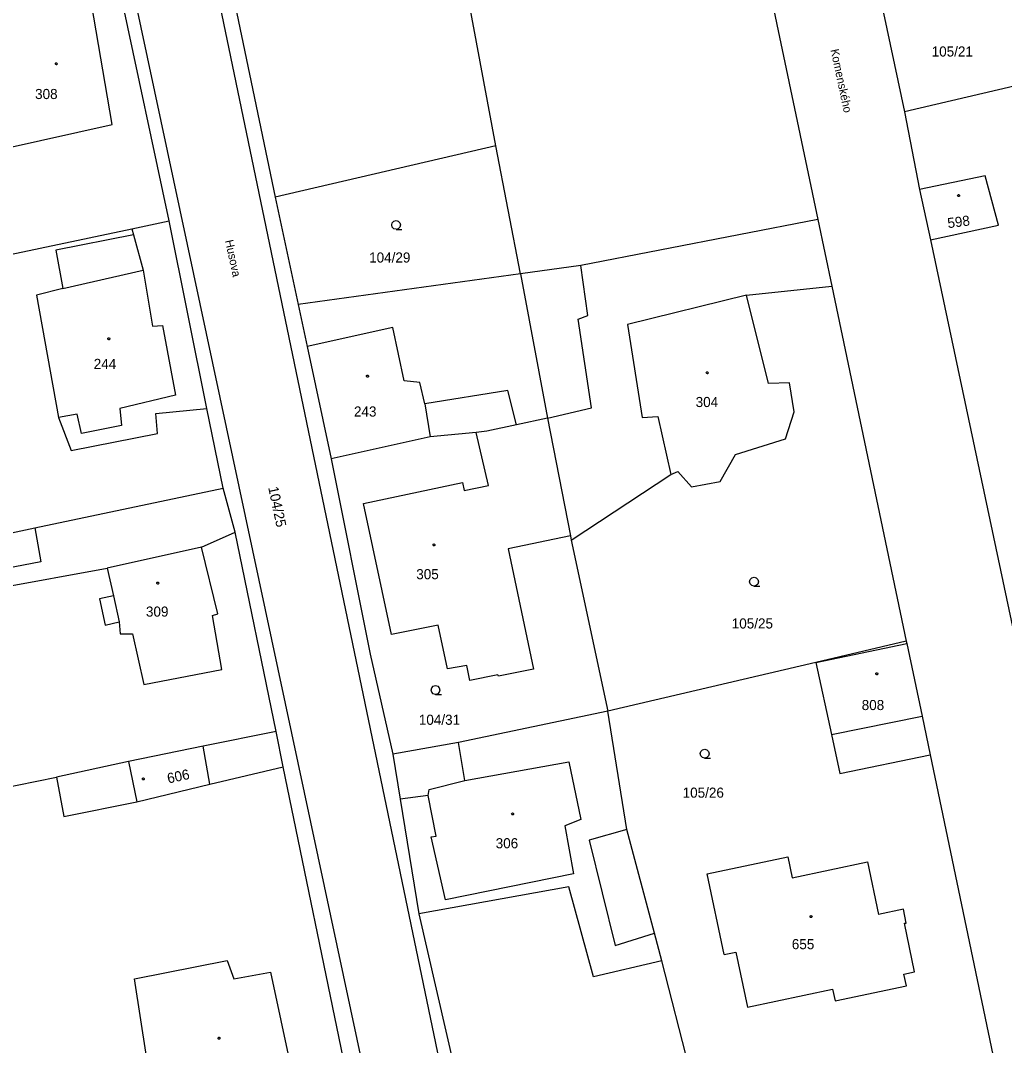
# Model space of a CAD drawing. Extents: x -757994 to -755874, y -1047691 to -1046119.
# Drawn here: x -756719.4 to -756636.5, y -1047241.1 to -1047154.8 of the extents above; entities that cross this region are included whole.
import ezdxf

# ---------------------------------------------------------------- set-up
doc = ezdxf.new("R2010")
doc.units = 0
doc.layers.add('katastrální mapa', color=7, linetype='Continuous')

msp = doc.modelspace()

# ---------------------------------------------------------------- linework, layer by layer
at = {"layer": 'katastrální mapa'}
for p, q in [((-756664.1, -1047115.15), (-756652.26, -1047171.56)), ((-756680.25, -1047261.01), (-756708.55, -1047124.95)), ((-756715.54, -1047126.13), (-756686.13, -1047263.87)), ((-756679.39, -1047165.36), (-756684.75, -1047136.4)), ((-756704.43, -1047138.76), (-756697.98, -1047169.68)), ((-756647.93, -1047148.48), (-756644.94, -1047162.5)), ((-756706.92, -1047171.68), (-756710.99, -1047152.52)), ((-756711.7, -1047163.55), (-756713.46, -1047153.37)), ((-756635.71, -1047160.32), (-756644.94, -1047162.5)), ((-756644.94, -1047162.5), (-756643.68, -1047169.02)), ((-756720.64, -1047165.55), (-756711.7, -1047163.55)), ((-756679.39, -1047165.36), (-756697.98, -1047169.68)), ((-756677.3, -1047176.13), (-756679.39, -1047165.36)), ((-756638.16, -1047167.89), (-756643.68, -1047169.02)), ((-756637.03, -1047172.04), (-756638.16, -1047167.89)), ((-756697.98, -1047169.68), (-756696.03, -1047178.72)), ((-756643.68, -1047169.02), (-756642.75, -1047173.28)), ((-756710.05, -1047172.34), (-756706.92, -1047171.68)), ((-756703.73, -1047187.47), (-756706.92, -1047171.68)), ((-756652.26, -1047171.56), (-756672.23, -1047175.43)), ((-756652.26, -1047171.56), (-756651.08, -1047177.17)), ((-756642.75, -1047173.28), (-756637.03, -1047172.04)), ((-756732.68, -1047177.09), (-756710.05, -1047172.34)), ((-756709.91, -1047172.84), (-756716.47, -1047174.14)), ((-756710.05, -1047172.34), (-756709.91, -1047172.84)), ((-756709.91, -1047172.84), (-756709.11, -1047175.82)), ((-756642.75, -1047173.28), (-756629.71, -1047234.91)), ((-756716.47, -1047174.14), (-756715.88, -1047177.36)), ((-756672.23, -1047175.43), (-756677.3, -1047176.13)), ((-756671.63, -1047179.65), (-756672.23, -1047175.43)), ((-756715.88, -1047177.36), (-756709.11, -1047175.82)), ((-756709.11, -1047175.82), (-756708.32, -1047180.53)), ((-756677.3, -1047176.13), (-756696.03, -1047178.72)), ((-756677.3, -1047176.13), (-756675.03, -1047188.29)), ((-756715.88, -1047177.36), (-756718.1, -1047177.93)), ((-756658.25, -1047177.94), (-756651.08, -1047177.17)), ((-756651.08, -1047177.17), (-756644.8, -1047207.08)), ((-756718.1, -1047177.93), (-756716.22, -1047188.23)), ((-756658.25, -1047177.94), (-756668.29, -1047180.39)), ((-756656.41, -1047185.36), (-756658.25, -1047177.94)), ((-756696.03, -1047178.72), (-756695.27, -1047182.26)), ((-756672.44, -1047179.95), (-756671.63, -1047179.65)), ((-756671.32, -1047187.43), (-756672.44, -1047179.95)), ((-756708.32, -1047180.53), (-756707.48, -1047180.47)), ((-756707.48, -1047180.47), (-756706.36, -1047186.34)), ((-756688.07, -1047180.64), (-756695.27, -1047182.26)), ((-756687.11, -1047185.15), (-756688.07, -1047180.64)), ((-756668.29, -1047180.39), (-756667.06, -1047188.23)), ((-756695.27, -1047182.26), (-756693.27, -1047191.71)), ((-756685.79, -1047185.27), (-756687.11, -1047185.15)), ((-756685.36, -1047187.08), (-756685.79, -1047185.27)), ((-756678.37, -1047185.95), (-756685.36, -1047187.08)), ((-756677.65, -1047188.85), (-756678.37, -1047185.95)), ((-756654.65, -1047185.32), (-756656.41, -1047185.36)), ((-756654.24, -1047187.74), (-756654.65, -1047185.32)), ((-756706.36, -1047186.34), (-756711.07, -1047187.46)), ((-756711.07, -1047187.46), (-756710.91, -1047188.9)), ((-756708.04, -1047187.9), (-756703.73, -1047187.47)), ((-756702.37, -1047194.18), (-756703.73, -1047187.47)), ((-756685.36, -1047187.08), (-756684.91, -1047189.85)), ((-756675.03, -1047188.29), (-756671.32, -1047187.43)), ((-756654.98, -1047190.04), (-756654.24, -1047187.74)), ((-756714.65, -1047187.96), (-756716.22, -1047188.23)), ((-756716.22, -1047188.23), (-756715.17, -1047191.02)), ((-756714.29, -1047189.57), (-756714.65, -1047187.96)), ((-756707.89, -1047189.58), (-756708.04, -1047187.9)), ((-756675.03, -1047188.29), (-756677.65, -1047188.85)), ((-756675.03, -1047188.29), (-756673.1, -1047198.2)), ((-756667.06, -1047188.23), (-756665.74, -1047188.14)), ((-756665.74, -1047188.14), (-756664.63, -1047193.02)), ((-756715.17, -1047191.02), (-756707.89, -1047189.58)), ((-756710.91, -1047188.9), (-756714.29, -1047189.57)), ((-756681.03, -1047189.48), (-756684.91, -1047189.85)), ((-756680.14, -1047189.39), (-756681.03, -1047189.48)), ((-756680, -1047193.95), (-756681.03, -1047189.48)), ((-756677.65, -1047188.85), (-756680.14, -1047189.39)), ((-756684.91, -1047189.85), (-756693.27, -1047191.71)), ((-756659.18, -1047191.36), (-756654.98, -1047190.04)), ((-756693.27, -1047191.71), (-756689.98, -1047208.15)), ((-756660.48, -1047193.61), (-756659.18, -1047191.36)), ((-756673.03, -1047198.55), (-756664.63, -1047193.02)), ((-756664.63, -1047193.02), (-756664.06, -1047192.79)), ((-756664.06, -1047192.79), (-756662.9, -1047194.06)), ((-756690.52, -1047195.47), (-756682.18, -1047193.71)), ((-756682.18, -1047193.71), (-756682.04, -1047194.38)), ((-756662.9, -1047194.06), (-756660.48, -1047193.61)), ((-756718.23, -1047197.51), (-756702.37, -1047194.18)), ((-756701.35, -1047197.89), (-756702.37, -1047194.18)), ((-756682.04, -1047194.38), (-756680, -1047193.95)), ((-756688.17, -1047206.5), (-756690.52, -1047195.47)), ((-756724.76, -1047198.92), (-756718.23, -1047197.51)), ((-756718.23, -1047197.51), (-756717.71, -1047200.39)), ((-756704.19, -1047199.16), (-756701.35, -1047197.89)), ((-756697.89, -1047214.67), (-756701.35, -1047197.89)), ((-756673.1, -1047198.2), (-756678.34, -1047199.29)), ((-756673.1, -1047198.2), (-756673.03, -1047198.55)), ((-756673.03, -1047198.55), (-756669.94, -1047212.95)), ((-756704.19, -1047199.16), (-756712.12, -1047200.91)), ((-756702.82, -1047204.76), (-756704.19, -1047199.16)), ((-756678.34, -1047199.29), (-756676.21, -1047209.42)), ((-756717.71, -1047200.39), (-756724.35, -1047201.65)), ((-756732.5, -1047204.62), (-756712.12, -1047200.91)), ((-756712.12, -1047200.91), (-756711.6, -1047203.25)), ((-756711.6, -1047203.25), (-756712.77, -1047203.51)), ((-756711.6, -1047203.25), (-756711.12, -1047205.45)), ((-756712.77, -1047203.51), (-756712.29, -1047205.71)), ((-756703.26, -1047204.91), (-756702.82, -1047204.76)), ((-756702.47, -1047209.46), (-756703.26, -1047204.91)), ((-756712.29, -1047205.71), (-756711.12, -1047205.45)), ((-756711.12, -1047205.45), (-756711.03, -1047206.46)), ((-756684.25, -1047205.72), (-756688.17, -1047206.5)), ((-756683.45, -1047209.4), (-756684.25, -1047205.72)), ((-756711.03, -1047206.46), (-756709.99, -1047206.45)), ((-756709.99, -1047206.45), (-756709.03, -1047210.72)), ((-756644.8, -1047207.08), (-756652.41, -1047208.86)), ((-756652.41, -1047208.86), (-756644.76, -1047207.26)), ((-756644.8, -1047207.08), (-756644.76, -1047207.26)), ((-756644.76, -1047207.26), (-756643.47, -1047213.38)), ((-756689.98, -1047208.15), (-756688.05, -1047216.58)), ((-756681.83, -1047209.12), (-756683.45, -1047209.4)), ((-756681.56, -1047210.39), (-756681.83, -1047209.12)), ((-756676.21, -1047209.42), (-756679.17, -1047210.02)), ((-756652.41, -1047208.86), (-756669.94, -1047212.95)), ((-756652.41, -1047208.86), (-756651.1, -1047214.94)), ((-756709.03, -1047210.72), (-756702.47, -1047209.46)), ((-756679.21, -1047209.89), (-756681.56, -1047210.39)), ((-756679.17, -1047210.02), (-756679.21, -1047209.89)), ((-756669.94, -1047212.95), (-756682.54, -1047215.61)), ((-756668.33, -1047222.93), (-756669.94, -1047212.95)), ((-756651.1, -1047214.94), (-756643.47, -1047213.38)), ((-756643.47, -1047213.38), (-756642.79, -1047216.64)), ((-756697.89, -1047214.67), (-756704.05, -1047215.9)), ((-756697.29, -1047217.65), (-756697.89, -1047214.67)), ((-756651.1, -1047214.94), (-756650.39, -1047218.22)), ((-756704.05, -1047215.9), (-756710.33, -1047217.21)), ((-756703.49, -1047219.12), (-756704.05, -1047215.9)), ((-756682.54, -1047215.61), (-756688.05, -1047216.58)), ((-756681.99, -1047218.79), (-756682.54, -1047215.61)), ((-756688.05, -1047216.58), (-756687.44, -1047220.36)), ((-756650.39, -1047218.22), (-756642.79, -1047216.64)), ((-756642.79, -1047216.64), (-756637.5, -1047241.9)), ((-756710.33, -1047217.21), (-756716.41, -1047218.52)), ((-756710.33, -1047217.21), (-756709.62, -1047220.59)), ((-756703.49, -1047219.12), (-756697.29, -1047217.65)), ((-756687.61, -1047264.59), (-756697.29, -1047217.65)), ((-756681.99, -1047218.79), (-756673.22, -1047217.23)), ((-756673.22, -1047217.23), (-756672.23, -1047222.1)), ((-756729.73, -1047221.2), (-756716.41, -1047218.52)), ((-756716.41, -1047218.52), (-756715.78, -1047221.82)), ((-756685.01, -1047219.55), (-756681.99, -1047218.79)), ((-756709.62, -1047220.59), (-756703.49, -1047219.12)), ((-756685.07, -1047220.06), (-756685.01, -1047219.55)), ((-756715.78, -1047221.82), (-756709.62, -1047220.59)), ((-756685.07, -1047220.06), (-756687.44, -1047220.36)), ((-756687.44, -1047220.36), (-756685.88, -1047230.02)), ((-756684.4, -1047223.49), (-756685.07, -1047220.06)), ((-756672.23, -1047222.1), (-756673.57, -1047222.62)), ((-756673.57, -1047222.62), (-756672.84, -1047226.65)), ((-756668.33, -1047222.93), (-756671.52, -1047223.84)), ((-756666.01, -1047231.67), (-756668.33, -1047222.93)), ((-756684.84, -1047223.55), (-756684.4, -1047223.49)), ((-756683.63, -1047228.86), (-756684.84, -1047223.55)), ((-756671.52, -1047223.84), (-756669.32, -1047232.7)), ((-756661.57, -1047226.66), (-756654.77, -1047225.24)), ((-756654.77, -1047225.24), (-756654.4, -1047227)), ((-756654.4, -1047227), (-756648.07, -1047225.66)), ((-756648.07, -1047225.66), (-756647.15, -1047230.09)), ((-756672.84, -1047226.65), (-756683.63, -1047228.86)), ((-756660.15, -1047233.46), (-756661.57, -1047226.66)), ((-756673.23, -1047227.76), (-756685.88, -1047230.02)), ((-756671.15, -1047235.33), (-756673.23, -1047227.76)), ((-756685.88, -1047230.02), (-756679.1, -1047259.48)), ((-756645.04, -1047229.65), (-756647.15, -1047230.09)), ((-756644.8, -1047230.83), (-756645.04, -1047229.65)), ((-756644.1, -1047234.92), (-756644.96, -1047230.83)), ((-756644.96, -1047230.83), (-756644.8, -1047230.83)), ((-756669.32, -1047232.7), (-756666.01, -1047231.67)), ((-756665.39, -1047234), (-756666.01, -1047231.67)), ((-756660.15, -1047233.46), (-756659.16, -1047233.25)), ((-756659.16, -1047233.25), (-756658.19, -1047237.88)), ((-756709.83, -1047235.51), (-756702.02, -1047233.96)), ((-756702.02, -1047233.96), (-756701.46, -1047235.5)), ((-756665.39, -1047234), (-756671.15, -1047235.33)), ((-756660.84, -1047251.74), (-756665.39, -1047234)), ((-756701.46, -1047235.5), (-756698.36, -1047234.94)), ((-756698.36, -1047234.94), (-756695.91, -1047246.38)), ((-756644.99, -1047235.11), (-756644.1, -1047234.92)), ((-756644.78, -1047236.09), (-756644.99, -1047235.11)), ((-756708.81, -1047242.06), (-756709.83, -1047235.51)), ((-756650.79, -1047237.35), (-756644.78, -1047236.09)), ((-756658.19, -1047237.88), (-756651, -1047236.37)), ((-756651, -1047236.37), (-756650.79, -1047237.35))]:
    msp.add_line(p, q, dxfattribs=at)
for points in [[(-756716.41, -1047158.355), (-756716.36, -1047158.365), (-756716.335, -1047158.41), (-756716.325, -1047158.44), (-756716.335, -1047158.485), (-756716.375, -1047158.52), (-756716.41, -1047158.525), (-756716.455, -1047158.51), (-756716.485, -1047158.48), (-756716.495, -1047158.44), (-756716.485, -1047158.395), (-756716.445, -1047158.36)], [(-756640.39, -1047169.455), (-756640.34, -1047169.465), (-756640.315, -1047169.51), (-756640.305, -1047169.54), (-756640.315, -1047169.585), (-756640.355, -1047169.62), (-756640.39, -1047169.625), (-756640.435, -1047169.61), (-756640.465, -1047169.58), (-756640.475, -1047169.54), (-756640.465, -1047169.495), (-756640.425, -1047169.46)], [(-756711.99, -1047181.515), (-756711.94, -1047181.525), (-756711.915, -1047181.57), (-756711.905, -1047181.6), (-756711.915, -1047181.645), (-756711.955, -1047181.68), (-756711.99, -1047181.685), (-756712.035, -1047181.67), (-756712.065, -1047181.64), (-756712.075, -1047181.6), (-756712.065, -1047181.555), (-756712.025, -1047181.52)], [(-756661.56, -1047184.375), (-756661.51, -1047184.385), (-756661.485, -1047184.43), (-756661.475, -1047184.46), (-756661.485, -1047184.505), (-756661.525, -1047184.54), (-756661.56, -1047184.545), (-756661.605, -1047184.53), (-756661.635, -1047184.5), (-756661.645, -1047184.46), (-756661.635, -1047184.415), (-756661.595, -1047184.38)], [(-756690.2, -1047184.665), (-756690.15, -1047184.675), (-756690.125, -1047184.72), (-756690.115, -1047184.75), (-756690.125, -1047184.795), (-756690.165, -1047184.83), (-756690.2, -1047184.835), (-756690.245, -1047184.82), (-756690.275, -1047184.79), (-756690.285, -1047184.75), (-756690.275, -1047184.705), (-756690.235, -1047184.67)], [(-756684.6, -1047198.875), (-756684.55, -1047198.885), (-756684.525, -1047198.93), (-756684.515, -1047198.96), (-756684.525, -1047199.005), (-756684.565, -1047199.04), (-756684.6, -1047199.045), (-756684.645, -1047199.03), (-756684.675, -1047199), (-756684.685, -1047198.96), (-756684.675, -1047198.915), (-756684.635, -1047198.88)], [(-756707.87, -1047202.095), (-756707.82, -1047202.105), (-756707.795, -1047202.15), (-756707.785, -1047202.18), (-756707.795, -1047202.225), (-756707.835, -1047202.26), (-756707.87, -1047202.265), (-756707.915, -1047202.25), (-756707.945, -1047202.22), (-756707.955, -1047202.18), (-756707.945, -1047202.135), (-756707.905, -1047202.1)], [(-756647.28, -1047209.725), (-756647.23, -1047209.735), (-756647.205, -1047209.78), (-756647.195, -1047209.81), (-756647.205, -1047209.855), (-756647.245, -1047209.89), (-756647.28, -1047209.895), (-756647.325, -1047209.88), (-756647.355, -1047209.85), (-756647.365, -1047209.81), (-756647.355, -1047209.765), (-756647.315, -1047209.73)], [(-756709.09, -1047218.585), (-756709.04, -1047218.595), (-756709.015, -1047218.64), (-756709.005, -1047218.67), (-756709.015, -1047218.715), (-756709.055, -1047218.75), (-756709.09, -1047218.755), (-756709.135, -1047218.74), (-756709.165, -1047218.71), (-756709.175, -1047218.67), (-756709.165, -1047218.625), (-756709.125, -1047218.59)], [(-756677.97, -1047221.535), (-756677.92, -1047221.545), (-756677.895, -1047221.59), (-756677.885, -1047221.62), (-756677.895, -1047221.665), (-756677.935, -1047221.7), (-756677.97, -1047221.705), (-756678.015, -1047221.69), (-756678.045, -1047221.66), (-756678.055, -1047221.62), (-756678.045, -1047221.575), (-756678.005, -1047221.54)], [(-756652.82, -1047230.175), (-756652.77, -1047230.185), (-756652.745, -1047230.23), (-756652.735, -1047230.26), (-756652.745, -1047230.305), (-756652.785, -1047230.34), (-756652.82, -1047230.345), (-756652.865, -1047230.33), (-756652.895, -1047230.3), (-756652.905, -1047230.26), (-756652.895, -1047230.215), (-756652.855, -1047230.18)], [(-756702.7, -1047240.425), (-756702.65, -1047240.435), (-756702.625, -1047240.48), (-756702.615, -1047240.51), (-756702.625, -1047240.555), (-756702.665, -1047240.59), (-756702.7, -1047240.595), (-756702.745, -1047240.58), (-756702.775, -1047240.55), (-756702.785, -1047240.51), (-756702.775, -1047240.465), (-756702.735, -1047240.43)]]:
    msp.add_lwpolyline(points, close=True, dxfattribs=at)
for points in [[(-756687.78, -1047172.38), (-756687.97, -1047172.33), (-756688.105, -1047172.195), (-756688.155, -1047172.01), (-756688.105, -1047171.825), (-756687.97, -1047171.69), (-756687.785, -1047171.64), (-756687.6, -1047171.69), (-756687.465, -1047171.825), (-756687.415, -1047172.015), (-756687.465, -1047172.205), (-756687.6, -1047172.34), (-756687.79, -1047172.39), (-756687.29, -1047172.39)], [(-756657.62, -1047202.43), (-756657.81, -1047202.38), (-756657.945, -1047202.245), (-756657.995, -1047202.06), (-756657.945, -1047201.875), (-756657.81, -1047201.74), (-756657.625, -1047201.69), (-756657.44, -1047201.74), (-756657.305, -1047201.875), (-756657.255, -1047202.065), (-756657.305, -1047202.255), (-756657.44, -1047202.39), (-756657.63, -1047202.44), (-756657.13, -1047202.44)], [(-756684.46, -1047211.55), (-756684.65, -1047211.5), (-756684.785, -1047211.365), (-756684.835, -1047211.18), (-756684.785, -1047210.995), (-756684.65, -1047210.86), (-756684.465, -1047210.81), (-756684.28, -1047210.86), (-756684.145, -1047210.995), (-756684.095, -1047211.185), (-756684.145, -1047211.375), (-756684.28, -1047211.51), (-756684.47, -1047211.56), (-756683.97, -1047211.56)], [(-756661.78, -1047216.91), (-756661.97, -1047216.86), (-756662.105, -1047216.725), (-756662.155, -1047216.54), (-756662.105, -1047216.355), (-756661.97, -1047216.22), (-756661.785, -1047216.17), (-756661.6, -1047216.22), (-756661.465, -1047216.355), (-756661.415, -1047216.545), (-756661.465, -1047216.735), (-756661.6, -1047216.87), (-756661.79, -1047216.92), (-756661.29, -1047216.92)]]:
    msp.add_lwpolyline(points, dxfattribs=at)

# ---------------------------------------------------------------- texts
for s, height, rotation, p in [('Komenského', 0.7, 282.06712, (-756651.184, -1047157.271)), ('598', 0.85, 7.44845, (-756641.272, -1047172.291)), ('Husova', 0.7, 282.06712, (-756702.2, -1047173.339)), ('104/25', 0.85, 281.95253, (-756698.566, -1047194.132)), ('606', 0.85, 12.14671, (-756706.978, -1047219.058))]:
    msp.add_text(s, height=height, rotation=rotation, dxfattribs=at).set_placement(p)
for s, p in [('105/21', (-756642.657, -1047157.83)), ('308', (-756718.204, -1047161.41)), ('104/29', (-756690.057, -1047175.18)), ('244', (-756713.264, -1047184.14)), ('304', (-756662.544, -1047187.35)), ('243', (-756691.337, -1047188.15)), ('305', (-756686.087, -1047201.85)), ('309', (-756708.864, -1047205)), ('105/25', (-756659.504, -1047206)), ('808', (-756648.554, -1047212.87)), ('104/31', (-756685.87, -1047214.11)), ('105/26', (-756663.641, -1047220.25)), ('306', (-756679.394, -1047224.51)), ('655', (-756654.442, -1047233.01))]:
    msp.add_text(s, height=0.85, dxfattribs=at).set_placement(p)

doc.saveas('drawing.dxf')
